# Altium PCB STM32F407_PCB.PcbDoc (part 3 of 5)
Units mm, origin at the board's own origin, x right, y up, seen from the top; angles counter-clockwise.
Board outline 100.27 x 100.27 mm, 2 copper layers (Top Layer, Bottom Layer); 134 components, 132 nets, 659 pads, 288 vias.
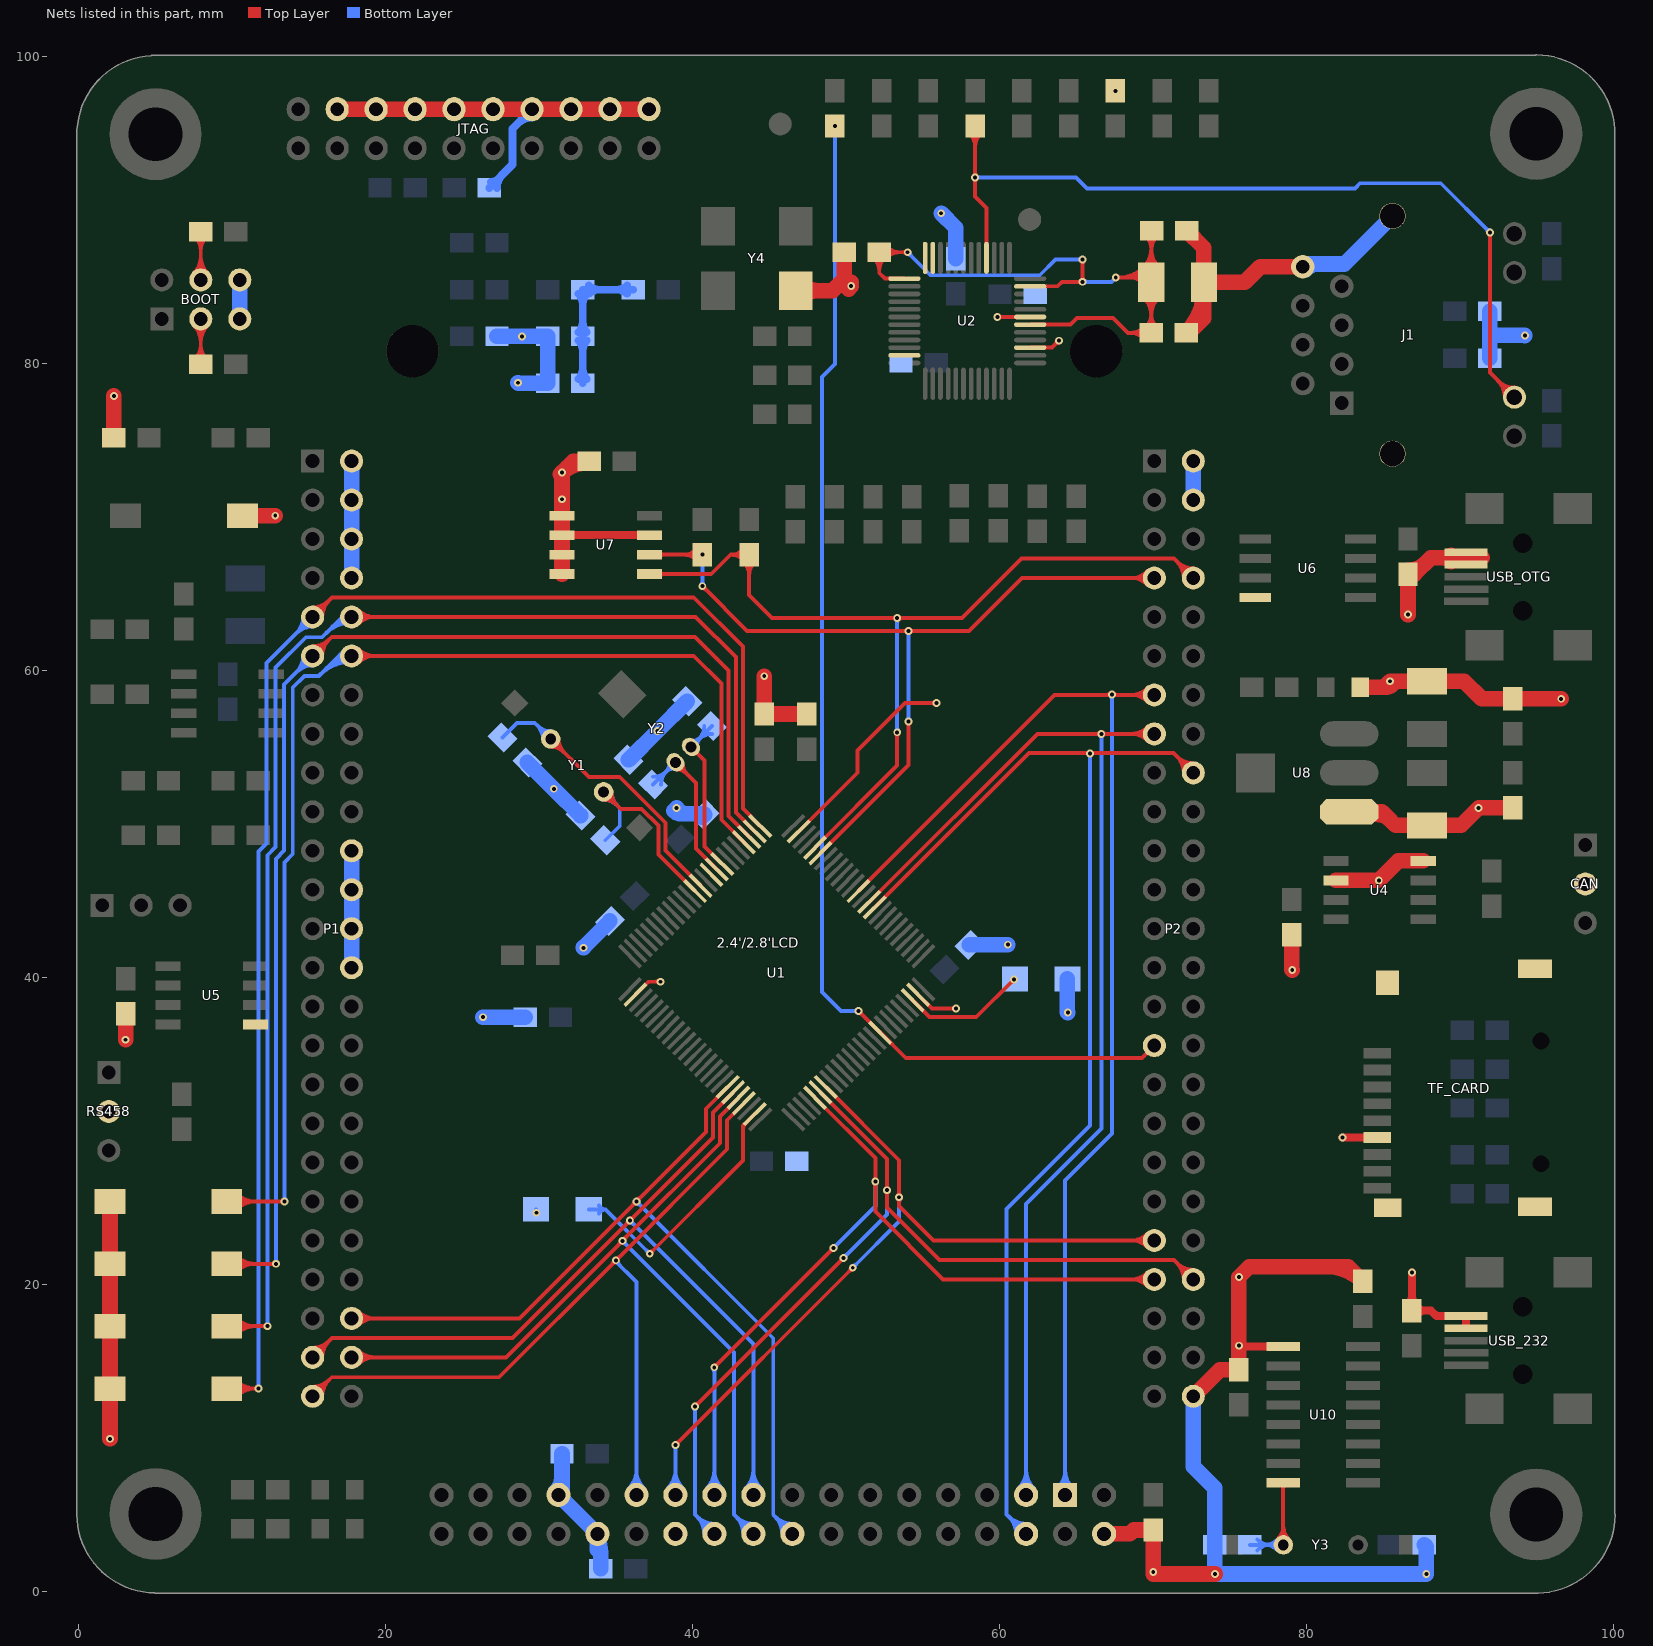
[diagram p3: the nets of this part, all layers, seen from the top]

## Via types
v1: diameter 0.508, hole 0.254, Top Layer to Bottom Layer, 288 vias

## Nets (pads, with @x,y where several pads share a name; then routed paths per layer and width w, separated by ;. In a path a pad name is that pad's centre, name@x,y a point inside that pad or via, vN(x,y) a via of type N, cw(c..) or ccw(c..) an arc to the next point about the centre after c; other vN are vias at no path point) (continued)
FSMC_D10: 2.4'/2.8'LCD.16 P1.46 U1.44 | length 76
  Top Layer w0.254: P1.46@17.78,17.78 28.715,17.78 v1(36.341,25.406) 40.869,29.933 40.869,31.444 U1.44@42.292,32.867 ; 18.671,17.78 cw(c18.671,18.671) 18.041,18.041 ccw(c18.671,18.671) 18.671,17.78 ; 18.671,17.78 ccw(c18.671,16.889) 18.041,17.519 cw(c18.671,16.889) 18.671,17.78 ; 19.284,17.78 cw(c19.284,19.284) 18.221,18.221 ccw(c19.284,19.284) 19.284,17.78 ; 19.284,17.78 ccw(c19.284,16.276) 18.221,17.339 cw(c19.284,16.276) 19.284,17.78 ; 36.125,25.189 cw(c36.341,24.972) 36.341,25.279 ccw(c36.341,24.972) 36.125,25.189 ; 36.125,25.189 ccw(c35.908,25.406) 36.214,25.406 cw(c35.908,25.406) 36.125,25.189 ; 36.558,25.623 cw(c36.341,25.84) 36.341,25.533 ccw(c36.341,25.84) 36.558,25.623 ; 36.558,25.623 ccw(c36.775,25.406) 36.468,25.406 cw(c36.775,25.406) 36.558,25.623
  Bottom Layer w0.254: v1(36.341,25.406) 45.263,16.485 45.263,4.978 2.4'/2.8'LCD.16@46.507,3.734 ; 36.558,25.189 cw(c36.775,25.406) 36.468,25.406 ccw(c36.775,25.406) 36.558,25.189 ; 36.558,25.189 ccw(c36.341,24.972) 36.341,25.279 cw(c36.341,24.972) 36.558,25.189 ; 45.38,4.861 cw(c44.253,3.734) 45.847,3.734 ccw(c44.253,3.734) 45.38,4.861 ; 45.38,4.861 ccw(c46.507,5.989) 46.507,4.394 cw(c46.507,5.989) 45.38,4.861 ; 45.814,4.428 cw(c45.12,3.734) 46.101,3.734 ccw(c45.12,3.734) 45.814,4.428 ; 45.814,4.428 ccw(c46.507,5.121) 46.507,4.14 cw(c46.507,5.121) 45.814,4.428
FSMC_D11: 2.4'/2.8'LCD.17 P1.47 U1.45 | length 75.2
  Top Layer w0.254: P1.47@15.24,15.24 16.51,16.51 28.272,16.51 v1(35.916,24.154) 41.326,29.564 41.326,31.194 U1.45@42.645,32.514 ; 15.87,15.87 cw(c15.24,16.5) 15.24,15.609 ccw(c15.24,16.5) 15.87,15.87 ; 15.87,15.87 ccw(c16.5,15.24) 15.609,15.24 cw(c16.5,15.24) 15.87,15.87 ; 16.304,16.304 cw(c15.24,17.367) 15.24,15.863 ccw(c15.24,17.367) 16.304,16.304 ; 16.304,16.304 ccw(c17.367,15.24) 15.863,15.24 cw(c17.367,15.24) 16.304,16.304 ; 35.699,23.937 cw(c35.916,23.72) 35.916,24.027 ccw(c35.916,23.72) 35.699,23.937 ; 35.699,23.937 ccw(c35.482,24.154) 35.789,24.154 cw(c35.482,24.154) 35.699,23.937 ; 36.132,24.371 cw(c35.916,24.588) 35.916,24.281 ccw(c35.916,24.588) 36.132,24.371 ; 36.132,24.371 ccw(c36.349,24.154) 36.043,24.154 cw(c36.349,24.154) 36.132,24.371
  Bottom Layer w0.254: v1@35.916,24.155 43.967,16.104 2.4'/2.8'LCD.17@43.967,6.274 ; 43.967,7.255 cw(c42.986,7.255) 43.68,6.561 ccw(c42.986,7.255) 43.967,7.255 ; 43.967,7.255 ccw(c44.949,7.255) 44.255,6.561 cw(c44.949,7.255) 43.967,7.255 ; 43.967,7.868 cw(c42.373,7.868) 43.5,6.741 ccw(c42.373,7.868) 43.967,7.868 ; 43.967,7.868 ccw(c45.562,7.868) 44.434,6.741 cw(c45.562,7.868) 43.967,7.868 ; v1@35.916,24.027 cw(c35.916,23.717) 36.135,23.936 ccw(c35.916,23.717) v1@35.916,24.027 ; v1@36.043,24.154 ccw(c36.346,24.154) 36.131,23.94 cw(c36.346,24.154) v1@36.043,24.154
FSMC_D12: 2.4'/2.8'LCD.18 P1.48 U1.46 | length 74.4
  Top Layer w0.254: P1.48@17.78,15.24 27.838,15.24 v1(35.433,22.835) ; v1@35.415,22.827 41.783,29.195 41.783,30.945 U1.46@42.999,32.16 ; 18.671,15.24 cw(c18.671,16.131) 18.041,15.501 ccw(c18.671,16.131) 18.671,15.24 ; 18.671,15.24 ccw(c18.671,14.349) 18.041,14.979 cw(c18.671,14.349) 18.671,15.24 ; 19.284,15.24 cw(c19.284,16.744) 18.221,15.681 ccw(c19.284,16.744) 19.284,15.24 ; 19.284,15.24 ccw(c19.284,13.736) 18.221,14.799 cw(c19.284,13.736) 19.284,15.24 ; 35.216,22.618 cw(c35.433,22.401) 35.433,22.708 ccw(c35.433,22.401) 35.216,22.618 ; 35.216,22.618 ccw(c34.999,22.835) 35.306,22.835 cw(c34.999,22.835) 35.216,22.618 ; v1@35.433,22.962 ccw(c35.433,23.242) 35.632,23.044 cw(c35.433,23.242) v1@35.433,22.962 ; v1@35.56,22.835 cw(c35.892,22.835) 35.657,23.07 ccw(c35.892,22.835) v1@35.56,22.835
  Bottom Layer w0.254: v1(35.433,22.835) 42.697,15.57 42.697,5.004 2.4'/2.8'LCD.18@43.967,3.734 ; 35.65,22.618 cw(c35.867,22.835) 35.56,22.835 ccw(c35.867,22.835) 35.65,22.618 ; 35.65,22.618 ccw(c35.433,22.401) 35.433,22.708 cw(c35.433,22.401) 35.65,22.618 ; 42.84,4.861 cw(c41.713,3.734) 43.307,3.734 ccw(c41.713,3.734) 42.84,4.861 ; 42.84,4.861 ccw(c43.967,5.989) 43.967,4.394 cw(c43.967,5.989) 42.84,4.861 ; 43.274,4.428 cw(c42.58,3.734) 43.561,3.734 ccw(c42.58,3.734) 43.274,4.428 ; 43.274,4.428 ccw(c43.967,5.121) 43.967,4.14 cw(c43.967,5.121) 43.274,4.428
FSMC_D13: 2.4'/2.8'LCD.19 P2.43 U1.55 | length 76.2
  Top Layer w0.254: v1(41.415,14.592) v1(49.187,22.365) ; U1.55@47.984,32.16 51.918,28.227 v1(51.918,26.695) 51.918,24.74 56.337,20.32 P2.43@70.104,20.32 ; 41.632,14.809 cw(c41.415,15.026) 41.415,14.719 ccw(c41.415,15.026) 41.632,14.809 ; 41.632,14.809 ccw(c41.848,14.592) 41.542,14.592 cw(c41.848,14.592) 41.632,14.809 ; 48.97,22.148 cw(c49.187,21.931) 49.187,22.238 ccw(c49.187,21.931) 48.97,22.148 ; 48.97,22.148 ccw(c48.753,22.365) 49.06,22.365 cw(c48.753,22.365) 48.97,22.148 ; 51.918,26.389 cw(c52.224,26.389) 52.007,26.606 ccw(c52.224,26.389) 51.918,26.389 ; 51.918,26.389 ccw(c51.611,26.389) 51.828,26.606 cw(c51.611,26.389) 51.918,26.389 ; 51.918,27.002 cw(c51.611,27.002) 51.828,26.785 ccw(c51.611,27.002) 51.918,27.002 ; 51.918,27.002 ccw(c52.224,27.002) 52.007,26.785 cw(c52.224,27.002) 51.918,27.002 ; 68.6,20.32 cw(c68.6,18.816) 69.663,19.879 ccw(c68.6,18.816) 68.6,20.32 ; 68.6,20.32 ccw(c68.6,21.824) 69.663,20.761 cw(c68.6,21.824) 68.6,20.32 ; 69.213,20.32 cw(c69.213,19.429) 69.843,20.059 ccw(c69.213,19.429) 69.213,20.32 ; 69.213,20.32 ccw(c69.213,21.211) 69.843,20.581 cw(c69.213,21.211) 69.213,20.32
  Bottom Layer w0.254: 2.4'/2.8'LCD.19@41.427,6.274 v1@41.427,14.592 ; v1(49.187,22.365) 51.918,25.095 v1(51.918,26.695) ; 41.427,7.255 cw(c40.446,7.255) 41.14,6.561 ccw(c40.446,7.255) 41.427,7.255 ; 41.427,7.255 ccw(c42.409,7.255) 41.715,6.561 cw(c42.409,7.255) 41.427,7.255 ; 41.427,7.868 cw(c39.833,7.868) 40.96,6.741 ccw(c39.833,7.868) 41.427,7.868 ; 41.427,7.868 ccw(c43.022,7.868) 41.894,6.741 cw(c43.022,7.868) 41.427,7.868 ; 49.404,22.582 cw(c49.187,22.798) 49.187,22.492 ccw(c49.187,22.798) 49.404,22.582 ; 49.404,22.582 ccw(c49.621,22.365) 49.314,22.365 cw(c49.621,22.365) 49.404,22.582 ; 51.918,26.389 cw(c52.224,26.389) 52.007,26.606 ccw(c52.224,26.389) 51.918,26.389 ; 51.918,26.389 ccw(c51.611,26.389) 51.828,26.606 cw(c51.611,26.389) 51.918,26.389 ; v1@41.325,14.502 cw(c41.077,14.255) 41.427,14.255 ccw(c41.077,14.255) v1@41.325,14.502 ; 41.427,14.316 cw(c41.691,14.316) 41.505,14.502 ccw(c41.691,14.316) 41.427,14.316
FSMC_D14: 2.4'/2.8'LCD.20 P2.44 U1.56 | length 81.7
  Top Layer w0.254: v1(40.157,12.04) v1(49.835,21.717) ; U1.56@48.338,32.514 52.68,28.172 v1(52.68,26.137) 52.68,25.019 56.109,21.59 71.374,21.59 P2.44@72.644,20.32 ; 40.374,12.256 cw(c40.157,12.473) 40.157,12.167 ccw(c40.157,12.473) 40.374,12.256 ; 40.374,12.256 ccw(c40.591,12.04) 40.284,12.04 cw(c40.591,12.04) 40.374,12.256 ; 49.618,21.5 cw(c49.835,21.283) 49.835,21.59 ccw(c49.835,21.283) 49.618,21.5 ; 49.618,21.5 ccw(c49.401,21.717) 49.708,21.717 cw(c49.401,21.717) 49.618,21.5 ; 52.68,25.83 cw(c52.986,25.83) 52.769,26.047 ccw(c52.986,25.83) 52.68,25.83 ; 52.68,25.83 ccw(c52.373,25.83) 52.59,26.047 cw(c52.373,25.83) 52.68,25.83 ; 52.68,26.443 cw(c52.373,26.443) 52.59,26.226 ccw(c52.373,26.443) 52.68,26.443 ; 52.68,26.443 ccw(c52.986,26.443) 52.769,26.226 cw(c52.986,26.443) 52.68,26.443 ; 71.58,21.384 cw(c70.517,20.32) 72.021,20.32 ccw(c70.517,20.32) 71.58,21.384 ; 71.58,21.384 ccw(c72.644,22.447) 72.644,20.943 cw(c72.644,22.447) 71.58,21.384 ; 72.014,20.95 cw(c71.384,20.32) 72.275,20.32 ccw(c71.384,20.32) 72.014,20.95 ; 72.014,20.95 ccw(c72.644,21.58) 72.644,20.689 cw(c72.644,21.58) 72.014,20.95
  Bottom Layer w0.254: v1(40.157,12.04) 40.157,5.004 2.4'/2.8'LCD.20@41.427,3.734 ; v1(49.835,21.717) 52.68,24.562 v1(52.68,26.137) ; 40.157,11.733 cw(c40.464,11.733) 40.247,11.95 ccw(c40.464,11.733) 40.157,11.733 ; 40.157,11.733 ccw(c39.851,11.733) 40.068,11.95 cw(c39.851,11.733) 40.157,11.733 ; 40.3,4.861 cw(c39.173,3.734) 40.767,3.734 ccw(c39.173,3.734) 40.3,4.861 ; 40.3,4.861 ccw(c41.427,5.989) 41.427,4.394 cw(c41.427,5.989) 40.3,4.861 ; 40.734,4.428 cw(c40.04,3.734) 41.021,3.734 ccw(c40.04,3.734) 40.734,4.428 ; 40.734,4.428 ccw(c41.427,5.121) 41.427,4.14 cw(c41.427,5.121) 40.734,4.428 ; 50.052,21.934 cw(c49.835,22.151) 49.835,21.844 ccw(c49.835,22.151) 50.052,21.934 ; 50.052,21.934 ccw(c50.268,21.717) 49.962,21.717 cw(c50.268,21.717) 50.052,21.934 ; 52.68,25.83 cw(c52.986,25.83) 52.769,26.047 ccw(c52.986,25.83) 52.68,25.83 ; 52.68,25.83 ccw(c52.373,25.83) 52.59,26.047 cw(c52.373,25.83) 52.68,25.83
FSMC_D15: 2.4'/2.8'LCD.21 P2.41 U1.57 | length 75.1
  Top Layer w0.254: v1(38.887,9.525) v1(50.444,21.082) ; U1.57@48.691,32.867 53.467,28.092 53.467,25.095 55.702,22.86 P2.41@70.104,22.86 ; 39.104,9.742 cw(c38.887,9.959) 38.887,9.652 ccw(c38.887,9.959) 39.104,9.742 ; 39.104,9.742 ccw(c39.321,9.525) 39.014,9.525 cw(c39.321,9.525) 39.104,9.742 ; 50.228,20.865 cw(c50.444,20.648) 50.444,20.955 ccw(c50.444,20.648) 50.228,20.865 ; 50.228,20.865 ccw(c50.011,21.082) 50.317,21.082 cw(c50.011,21.082) 50.228,20.865 ; 53.467,25.373 cw(c53.774,25.373) 53.557,25.59 ccw(c53.774,25.373) 53.467,25.373 ; 53.467,25.373 ccw(c53.16,25.373) 53.377,25.59 cw(c53.16,25.373) 53.467,25.373 ; 53.467,25.986 cw(c53.16,25.986) 53.377,25.769 ccw(c53.16,25.986) 53.467,25.986 ; 53.467,25.986 ccw(c53.774,25.986) 53.557,25.769 cw(c53.774,25.986) 53.467,25.986 ; 68.6,22.86 cw(c68.6,21.356) 69.663,22.419 ccw(c68.6,21.356) 68.6,22.86 ; 68.6,22.86 ccw(c68.6,24.364) 69.663,23.301 cw(c68.6,24.364) 68.6,22.86 ; 69.213,22.86 cw(c69.213,21.969) 69.843,22.599 ccw(c69.213,21.969) 69.213,22.86 ; 69.213,22.86 ccw(c69.213,23.751) 69.843,23.121 cw(c69.213,23.751) 69.213,22.86
  Bottom Layer w0.254: 2.4'/2.8'LCD.21@38.887,6.274 v1(38.887,9.525) ; v1(50.444,21.082) 53.467,24.105 v1(53.467,25.679) ; 38.887,7.255 cw(c37.906,7.255) 38.6,6.561 ccw(c37.906,7.255) 38.887,7.255 ; 38.887,7.255 ccw(c39.869,7.255) 39.175,6.561 cw(c39.869,7.255) 38.887,7.255 ; 38.887,7.868 cw(c37.293,7.868) 38.42,6.741 ccw(c37.293,7.868) 38.887,7.868 ; 38.887,7.868 ccw(c40.482,7.868) 39.354,6.741 cw(c40.482,7.868) 38.887,7.868 ; 38.887,9.218 cw(c39.194,9.218) 38.977,9.435 ccw(c39.194,9.218) 38.887,9.218 ; 38.887,9.218 ccw(c38.581,9.218) 38.798,9.435 cw(c38.581,9.218) 38.887,9.218 ; 50.661,21.299 cw(c50.444,21.516) 50.444,21.209 ccw(c50.444,21.516) 50.661,21.299 ; 50.661,21.299 ccw(c50.878,21.082) 50.571,21.082 cw(c50.878,21.082) 50.661,21.299 ; 53.467,25.373 cw(c53.774,25.373) 53.557,25.59 ccw(c53.774,25.373) 53.467,25.373 ; 53.467,25.373 ccw(c53.16,25.373) 53.377,25.59 cw(c53.16,25.373) 53.467,25.373
FSMC_NE1: 2.4'/2.8'LCD.1 P2.13 U1.88 | length 95.8
  Top Layer w0.254: U1.88@50.812,45.631 63.602,58.42 P2.13@70.104,58.42 ; 68.6,58.42 cw(c68.6,56.916) 69.663,57.979 ccw(c68.6,56.916) 68.6,58.42 ; 68.6,58.42 ccw(c68.6,59.924) 69.663,58.861 cw(c68.6,59.924) 68.6,58.42 ; 69.213,58.42 cw(c69.213,57.529) 69.843,58.159 ccw(c69.213,57.529) 69.213,58.42 ; 69.213,58.42 ccw(c69.213,59.311) 69.843,58.681 cw(c69.213,59.311) 69.213,58.42 ; 66.967,58.42 ccw(c66.967,58.813) 67.246,58.535 cw(c66.967,58.813) 66.967,58.42 ; v1@67.425,58.535 ccw(c67.703,58.813) 67.703,58.42 cw(c67.703,58.813) v1@67.425,58.535
  Bottom Layer w0.254: 2.4'/2.8'LCD.1@64.287,6.274 64.287,26.772 67.335,29.82 v1(67.335,58.445) ; 64.287,7.255 cw(c63.306,7.255) 64,6.561 ccw(c63.306,7.255) 64.287,7.255 ; 64.287,7.255 ccw(c65.269,7.255) 64.575,6.561 cw(c65.269,7.255) 64.287,7.255 ; 64.287,7.868 cw(c62.693,7.868) 63.82,6.741 ccw(c62.693,7.868) 64.287,7.868 ; 64.287,7.868 ccw(c65.882,7.868) 64.754,6.741 cw(c65.882,7.868) 64.287,7.868 ; 67.335,58.139 cw(c67.642,58.139) 67.425,58.356 ccw(c67.642,58.139) 67.335,58.139 ; 67.335,58.139 ccw(c67.029,58.139) 67.246,58.356 cw(c67.029,58.139) 67.335,58.139
FSMC_NOE: 2.4'/2.8'LCD.4 P2.18 U1.85 | length 96.9
  Top Layer w0.254: U1.85@51.873,44.57 61.938,54.635 71.349,54.635 P2.18@72.644,53.34 ; 71.58,54.404 cw(c70.517,53.34) 72.021,53.34 ccw(c70.517,53.34) 71.58,54.404 ; 71.58,54.404 ccw(c72.644,55.467) 72.644,53.963 cw(c72.644,55.467) 71.58,54.404 ; 72.014,53.97 cw(c71.384,53.34) 72.275,53.34 ccw(c71.384,53.34) 72.014,53.97 ; 72.014,53.97 ccw(c72.644,54.6) 72.644,53.709 cw(c72.644,54.6) 72.014,53.97 ; 65.545,54.635 cw(c65.545,54.242) 65.823,54.52 ccw(c65.545,54.242) 65.545,54.635 ; v1@66.003,54.52 cw(c66.281,54.242) 66.281,54.635 ccw(c66.281,54.242) v1@66.003,54.52
  Bottom Layer w0.254: 2.4'/2.8'LCD.4@61.747,3.734 60.477,5.004 60.477,24.917 65.913,30.353 v1(65.913,54.61) ; 60.62,4.861 cw(c59.493,3.734) 61.087,3.734 ccw(c59.493,3.734) 60.62,4.861 ; 60.62,4.861 ccw(c61.747,5.989) 61.747,4.394 cw(c61.747,5.989) 60.62,4.861 ; 61.054,4.428 cw(c60.36,3.734) 61.341,3.734 ccw(c60.36,3.734) 61.054,4.428 ; 61.054,4.428 ccw(c61.747,5.121) 61.747,4.14 cw(c61.747,5.121) 61.054,4.428 ; 65.913,54.303 cw(c66.22,54.303) 66.003,54.52 ccw(c66.22,54.303) 65.913,54.303 ; 65.913,54.303 ccw(c65.606,54.303) 65.823,54.52 cw(c65.606,54.303) 65.913,54.303
FSMC_NWE: 2.4'/2.8'LCD.3 P2.15 U1.86 | length 93.3
  Top Layer w0.254: U1.86@51.519,44.924 62.476,55.88 v1(66.65,55.88) P2.15@70.104,55.88 ; 66.343,55.88 cw(c66.343,55.573) 66.56,55.79 ccw(c66.343,55.573) 66.343,55.88 ; 66.343,55.88 ccw(c66.343,56.187) 66.56,55.97 cw(c66.343,56.187) 66.343,55.88 ; 66.956,55.88 cw(c66.956,56.187) 66.739,55.97 ccw(c66.956,56.187) 66.956,55.88 ; 66.956,55.88 ccw(c66.956,55.573) 66.739,55.79 cw(c66.956,55.573) 66.956,55.88 ; 68.6,55.88 cw(c68.6,54.376) 69.663,55.439 ccw(c68.6,54.376) 68.6,55.88 ; 68.6,55.88 ccw(c68.6,57.384) 69.663,56.321 cw(c68.6,57.384) 68.6,55.88 ; 69.213,55.88 cw(c69.213,54.989) 69.843,55.619 ccw(c69.213,54.989) 69.213,55.88 ; 69.213,55.88 ccw(c69.213,56.771) 69.843,56.141 cw(c69.213,56.771) 69.213,55.88
  Bottom Layer w0.254: 2.4'/2.8'LCD.3@61.747,6.274 61.747,25.248 66.65,30.15 v1(66.65,55.88) ; 61.747,7.255 cw(c60.766,7.255) 61.46,6.561 ccw(c60.766,7.255) 61.747,7.255 ; 61.747,7.255 ccw(c62.729,7.255) 62.035,6.561 cw(c62.729,7.255) 61.747,7.255 ; 61.747,7.868 cw(c60.153,7.868) 61.28,6.741 ccw(c60.153,7.868) 61.747,7.868 ; 61.747,7.868 ccw(c63.342,7.868) 62.214,6.741 cw(c63.342,7.868) 61.747,7.868 ; 66.65,55.573 cw(c66.956,55.573) 66.739,55.79 ccw(c66.956,55.573) 66.65,55.573 ; 66.65,55.573 ccw(c66.343,55.573) 66.56,55.79 cw(c66.343,55.573) 66.65,55.573
GND: 2.4'/2.8'LCD.22 2.4'/2.8'LCD.26 2.4'/2.8'LCD.27 2.4'/2.8'LCD.36 BOOT.5 BOOT.6 C1.1 C2.2 C3.2 C4.2 C5.2 C6.2 C7.2 C8.2 C9.2 C10.2 C11.2 C12.2 C13.1 C14.1 C15.2 C16.1 C17.1 C18.1 C20.2 C21.2 C22.2 C23.2 C24.2 C25.2 C26.2 C27.2 C28.2 C29.1 C30.1 C31.1 C32.2 C33.2 C36.1 C37.2 C38.2 C39.2 C40.2 C41.2 C42.1 C43.1 C44.2 CAN.2 DS0.2 J1.8 J1.13 J1.14 JTAG.4 JTAG.6 JTAG.8 JTAG.10 JTAG.12 JTAG.14 JTAG.16 JTAG.18 JTAG.20 K1.2 K2.2 K3.2 K4.2 P1.2 P1.4 P1.6 P1.8 P1.22 P1.24 P1.26 P1.28 P2.2 P2.4 P2.50 R3.2 R16.1 R32.1 RESET.2 RS458.2 TF_CARD.6 TF_CARD.10 TF_CARD.11 TF_CARD.12 TF_CARD.13 U1.10 U1.27 U1.74 U1.99 U2.15 U2.19 U2.35 U2.36 U2.47 U4.2 U4.8 U5.5 U6.4 U7.1 U7.2 U7.3 U7.4 U7.7 U8.1 U10.1 USB_232.4 USB_232.5 USB_OTG.4 USB_OTG.5 Y4.2 | length 374.5
  Top Layer w0.254: U1.27@36.281,38.878 37.129,39.726 v1(37.922,39.726) ; U1.99@46.923,49.52 50.749,53.346 50.749,54.788 53.848,57.887 v1(55.905,57.887) ; U1.74@54.701,38.878 55.606,37.973 v1(57.175,37.973) ; v1(59.868,83.058) 59.872,83.054 U2.19@62.012,83.054 ; U2.15@62.012,81.054 63.426,81.054 v1(63.881,81.509) ; 37.616,39.726 cw(c37.616,39.419) 37.832,39.636 ccw(c37.616,39.419) 37.616,39.726 ; 37.616,39.726 ccw(c37.616,40.032) 37.832,39.815 cw(c37.616,40.032) 37.616,39.726 ; 55.599,57.887 cw(c55.599,57.58) 55.816,57.797 ccw(c55.599,57.58) 55.599,57.887 ; 55.599,57.887 ccw(c55.599,58.193) 55.816,57.976 cw(c55.599,58.193) 55.599,57.887 ; 56.869,37.973 cw(c56.869,37.666) 57.086,37.883 ccw(c56.869,37.666) 56.869,37.973 ; 56.869,37.973 ccw(c56.869,38.28) 57.086,38.063 cw(c56.869,38.28) 56.869,37.973 ; 63.664,81.292 cw(c63.881,81.075) 63.881,81.382 ccw(c63.881,81.075) 63.664,81.292 ; 63.664,81.292 ccw(c63.447,81.509) 63.754,81.509 cw(c63.447,81.509) 63.664,81.292 ; v1@59.958,82.968 cw(c60.165,82.761) 60.165,83.054 ccw(c60.165,82.761) v1@59.958,82.968 ; v1@59.958,83.148 ccw(c60.184,83.374) 60.184,83.054 cw(c60.184,83.374) v1@59.958,83.148
  Top Layer w0.508: U7.2@31.496,68.834 U7.7@37.196,68.834 ; v1@75.617,15.951 U10.1@78.502,15.951 ; v1(82.372,29.566) 82.374,29.564 TF_CARD.6@84.633,29.564 ; v1(86.893,20.777) 86.892,20.776 C42.1@86.892,18.288 88.138,18.288 88.494,17.932 USB_232.5@90.424,17.932 USB_232.4@90.424,17.132 ; 86.892,19.335 cw(c85.972,19.335) 86.622,18.684 ccw(c85.972,19.335) 86.892,19.335 ; 86.892,19.335 ccw(c87.812,19.335) 87.161,18.684 cw(c87.812,19.335) 86.892,19.335 ; 87.812,18.288 cw(c87.812,19.208) 87.161,18.557 ccw(c87.812,19.208) 87.812,18.288 ; 87.812,18.288 ccw(c87.812,17.368) 87.161,18.019 cw(c87.812,17.368) 87.812,18.288
  Top Layer w1.016: v1(2.032,9.931) K4.2@2.032,25.4 ; C7.2@2.286,75.186 v1(2.286,77.902) ; C37.2@3.046,37.643 3.046,35.943 v1(3.048,35.941) ; RESET.2@10.668,70.104 v1(12.802,70.104) ; JTAG.4@16.84,96.596 JTAG.10@24.46,96.596 JTAG.12@27,96.596 JTAG.16@32.08,96.596 JTAG.18@34.62,96.596 JTAG.20@37.16,96.596 ; U7.4@31.496,66.294 U7.3@31.496,67.564 U7.2@31.496,68.834 U7.1@31.496,70.104 v1(31.496,71.171) v1(31.496,72.923) 32.234,73.662 C39.2@33.274,73.662 ; v1(44.677,59.641) C13.1@44.677,57.175 C14.1@47.446,57.175 ; Y4.2@46.736,84.768 49.132,84.768 49.886,85.522 ; C20.2@49.886,87.276 49.886,85.522 ; v1(50.343,85.065) 49.886,85.522 ; 2.4'/2.8'LCD.36@66.827,3.734 68.504,3.734 68.758,3.988 C30.1@70.029,3.988 v1(70.029,1.246) 70.029,1.118 v1(74.066,1.118) ; C21.2@72.187,82.015 72.363,82.015 73.33,82.982 C23.2@73.33,85.319 ; C22.2@72.212,88.67 73.33,87.552 C23.2@73.33,85.319 ; P2.50@72.644,12.7 74.371,14.427 C44.2@75.617,14.427 75.617,15.292 v1(75.617,16.002) v1(75.617,20.474) 76.302,21.158 82.726,21.158 C43.1@83.691,20.193 ; C36.1@79.072,42.799 79.072,40.511 v1(79.096,40.488) ; J1.8@79.781,86.33 77.008,86.33 75.997,85.319 C23.2@73.33,85.319 ; U4.2@81.94,46.33 v1(84.734,46.33) 86.004,47.6 U4.8@87.64,47.6 ; U8.1@82.806,50.801 84.937,50.801 85.827,49.911 C10.2@87.884,49.911 90.094,49.911 v1(91.237,51.054) C11.2@93.47,51.054 ; DS0.2@83.515,58.928 85.09,58.928 ; v1(86.639,63.652) 86.638,63.654 C38.2@86.638,66.294 87.071,66.294 88.138,67.361 91.465,67.361 ; v1(96.622,58.166) 91.44,58.166 90.297,59.309 C8.2@87.884,59.309 v1(85.471,59.309) ; 48.165,84.768 cw(c48.165,86.197) 47.155,85.187 ccw(c48.165,86.197) 48.165,84.768 ; 48.165,84.768 ccw(c48.165,83.339) 47.155,84.349 cw(c48.165,83.339) 48.165,84.768 ; 49.886,85.522 ccw(c50.756,85.522) 50.173,84.876 cw(c50.756,85.522) 49.886,85.522 ; 85.09,58.928 v1(85.471,59.309) ; 85.09,58.928 v1(85.471,59.309) ; 85.164,58.928 ccw(c85.164,59.616) v1@85.651,59.129 ; 85.164,58.928 ccw(c85.164,59.616) v1@85.651,59.129 ; 85.164,58.928 ccw(c85.164,59.616) v1@85.651,59.129 ; 85.164,58.928 ccw(c85.164,59.616) v1@85.651,59.129 ; v1@31.372,72.799 cw(c33.147,71.024) 33.147,73.535 ccw(c33.147,71.024) v1@31.372,72.799 ; 31.778,73.205 cw(c32.724,72.259) 33.11,73.54 ccw(c32.724,72.259) 31.778,73.205 ; 49.215,84.852 cw(c50.343,83.724) 50.343,85.319 ccw(c50.343,83.724) 49.215,84.852 ; 49.886,85.555 ccw(c50.833,85.555) 50.163,84.885 cw(c50.833,85.555) 49.886,85.555 ; C21.2@72.224,82.105 ccw(c69.554,84.774) 73.33,84.774 cw(c69.554,84.774) C21.2@72.224,82.105 ; 81.361,21.158 cw(c81.361,17.99) 83.602,20.23 ccw(c81.361,17.99) 81.361,21.158 ; U8.1@84.024,50.515 cw(c84.575,49.387) 85.463,50.275 ccw(c84.575,49.387) U8.1@84.024,50.515 ; C38.2@86.638,66.548 ccw(c86.638,68.208) 87.811,67.034 cw(c86.638,68.208) C38.2@86.638,66.548 ; 88.823,67.361 cw(c88.823,66.465) 89.456,67.098 ccw(c88.823,66.465) 88.823,67.361 ; 89.039,67.361 ccw(c89.039,67.95) 89.456,67.534 cw(c89.039,67.95) 89.039,67.361
  Bottom Layer w0.254: C5.2@29.809,24.881 29.809,24.674 v1(29.82,24.663) C5.2@29.82,24.638
  Bottom Layer w0.508: P1.6@17.78,68.58 P1.4@17.78,71.12 ; R3.2@26.746,91.467 28.27,92.991 28.27,95.326 JTAG.14@29.54,96.596 ; 17.78,69.777 cw(c16.583,69.777) 17.429,68.931 ccw(c16.583,69.777) 17.78,69.777 ; 17.78,69.777 ccw(c18.977,69.777) 18.131,68.931 cw(c18.977,69.777) 17.78,69.777 ; 17.78,69.923 cw(c18.977,69.923) 18.131,70.769 ccw(c18.977,69.923) 17.78,69.923 ; 17.78,69.923 ccw(c16.583,69.923) 17.429,70.769 cw(c16.583,69.923) 17.78,69.923 ; R3.2@26.873,91.848 ccw(c26.873,92.461) 27.307,92.028 cw(c26.873,92.461) R3.2@26.873,91.848 ; R3.2@27.254,91.467 cw(c28.481,91.467) 27.613,92.334 ccw(c28.481,91.467) R3.2@27.254,91.467 ; 28.63,95.686 cw(c29.54,94.775) 29.54,96.063 ccw(c29.54,94.775) 28.63,95.686 ; 28.72,95.776 ccw(c27.937,96.559) 29.044,96.559 cw(c27.937,96.559) 28.72,95.776
  Bottom Layer w1.016: BOOT.5@10.49,82.931 BOOT.6@10.49,85.471 ; P1.28@17.78,40.64 P1.26@17.78,43.18 P1.24@17.78,45.72 P1.22@17.78,48.26 ; P1.8@17.78,66.04 P1.6@17.78,68.58 P1.4@17.78,71.12 P1.2@17.78,73.66 ; v1(26.34,37.414) 26.341,37.413 C12.2@29.108,37.413 ; R32.1@27.254,81.786 v1(28.88,81.786) C32.2@30.556,81.786 C33.2@30.556,78.738 28.653,78.738 v1(28.626,78.765) ; C1.1@29.234,54.025 v1(30.961,52.297) C2.2@32.698,50.561 ; 2.4'/2.8'LCD.27@31.267,6.274 2.4'/2.8'LCD.26@33.807,3.734 33.807,2.692 34.011,2.489 C29.1@34.011,1.449 ; 2.4'/2.8'LCD.27@31.496,6.502 C31.1@31.496,8.968 ; v1(32.893,41.935) 32.893,41.963 C16.1@34.619,43.689 ; C4.2@35.822,54.193 35.847,54.193 v1(37.728,56.074) C3.2@39.657,58.003 ; v1(38.964,51.054) 39.339,50.678 40.736,50.678 C17.1@40.794,50.621 ; v1(56.21,89.814) 57.148,88.876 C25.2@57.148,86.843 ; C15.2@58.054,42.131 60.546,42.131 v1(60.554,42.139) ; C6.2@64.44,39.903 64.44,37.744 v1(64.465,37.719) ; P2.50@72.644,12.7 72.644,8.128 74.041,6.731 C40.2@74.041,3.021 74.041,1.143 v1(74.066,1.118) v1(87.833,1.118) 87.833,2.897 C41.2@87.706,3.024 ; P2.4@72.644,71.12 P2.2@72.644,73.66 ; J1.8@79.781,86.33 79.959,86.507 82.491,86.507 J1.14@85.623,89.64 ; C28.2@91.973,80.367 91.973,81.864 ; C27.2@91.973,83.415 91.973,81.864 ; v1(94.259,81.839) 94.234,81.864 91.973,81.864 ; 2.4'/2.8'LCD.26@33.61,3.536 cw(c32.642,2.569) 34.011,2.569 ; 2.4'/2.8'LCD.26@33.61,3.536 cw(c32.642,2.569) 34.011,2.569 ; 2.4'/2.8'LCD.26@33.61,3.536 cw(c32.642,2.569) 34.011,2.569 ; 2.4'/2.8'LCD.26@33.61,3.536 cw(c32.642,2.569) 34.011,2.569 ; 38.784,50.874 ccw(c39.258,51.348) 39.258,50.678 ; 38.784,50.874 ccw(c39.258,51.348) 39.258,50.678 ; 38.784,50.874 ccw(c39.258,51.348) 39.258,50.678 ; 38.784,50.874 ccw(c39.258,51.348) 39.258,50.678 ; 2.4'/2.8'LCD.27@31.07,6.471 ccw(c30.041,7.5) 31.496,7.5 cw(c30.041,7.5) 2.4'/2.8'LCD.27@31.07,6.471 ; C17.1@40.042,50.678 cw(c40.042,49.87) 40.614,50.441 ccw(c40.042,49.87) C17.1@40.042,50.678 ; J1.8@79.961,86.15 cw(c80.824,85.287) 80.824,86.507 ccw(c80.824,85.287) J1.8@79.961,86.15
  other v1: 67.564,97.79
IIC_SCL: P2.7 R38.1 U1.95 U7.6 | length 76
  Top Layer w0.254: U7.6@37.196,67.564 v1(40.642,67.564) ; v1(40.64,65.507) 43.561,62.586 58.014,62.586 61.468,66.04 P2.7@70.104,66.04 ; U1.95@48.338,48.106 54.077,53.845 v1(54.077,56.693) ; 38.164,67.564 cw(c38.164,68.024) 37.839,67.699 ccw(c38.164,68.024) 38.164,67.564 ; 38.164,67.564 ccw(c38.164,67.104) 37.839,67.429 cw(c38.164,67.104) 38.164,67.564 ; 39.415,67.564 cw(c39.415,66.338) 40.282,67.205 ccw(c39.415,66.338) 39.415,67.564 ; 39.415,67.564 ccw(c39.415,68.79) 40.282,67.923 cw(c39.415,68.79) 39.415,67.564 ; R38.1@40.335,67.564 cw(c40.335,67.257) 40.552,67.474 ccw(c40.335,67.257) R38.1@40.335,67.564 ; R38.1@40.335,67.564 ccw(c40.335,67.871) 40.552,67.654 cw(c40.335,67.871) R38.1@40.335,67.564 ; 40.857,65.29 cw(c41.074,65.507) 40.767,65.507 ccw(c41.074,65.507) 40.857,65.29 ; 40.857,65.29 ccw(c40.64,65.073) 40.64,65.38 cw(c40.64,65.073) 40.857,65.29 ; 53.77,62.586 cw(c53.77,62.279) 53.987,62.496 ccw(c53.77,62.279) 53.77,62.586 ; 53.77,62.586 ccw(c53.77,62.892) 53.987,62.675 cw(c53.77,62.892) 53.77,62.586 ; 54.077,56.386 cw(c54.383,56.386) 54.166,56.603 ccw(c54.383,56.386) 54.077,56.386 ; 54.077,56.386 ccw(c53.77,56.386) 53.987,56.603 cw(c53.77,56.386) 54.077,56.386 ; 54.383,62.586 cw(c54.383,62.892) 54.166,62.675 ccw(c54.383,62.892) 54.383,62.586 ; 54.383,62.586 ccw(c54.383,62.279) 54.166,62.496 cw(c54.383,62.279) 54.383,62.586 ; 68.6,66.04 cw(c68.6,64.536) 69.663,65.599 ccw(c68.6,64.536) 68.6,66.04 ; 68.6,66.04 ccw(c68.6,67.544) 69.663,66.481 cw(c68.6,67.544) 68.6,66.04 ; 69.213,66.04 cw(c69.213,65.149) 69.843,65.779 ccw(c69.213,65.149) 69.213,66.04 ; 69.213,66.04 ccw(c69.213,66.931) 69.843,66.301 cw(c69.213,66.931) 69.213,66.04
  Bottom Layer w0.254: v1(40.64,65.507) 40.642,65.508 v1(40.642,67.564) ; v1(54.077,56.693) v1(54.077,62.586) ; 40.642,67.257 cw(c40.948,67.257) 40.731,67.474 ccw(c40.948,67.257) 40.642,67.257 ; 40.642,67.257 ccw(c40.335,67.257) 40.552,67.474 cw(c40.335,67.257) 40.642,67.257 ; 54.077,56.999 cw(c53.77,56.999) 53.987,56.783 ccw(c53.77,56.999) 54.077,56.999 ; 54.077,56.999 ccw(c54.383,56.999) 54.166,56.783 cw(c54.383,56.999) 54.077,56.999 ; 54.077,62.279 cw(c54.383,62.279) 54.166,62.496 ccw(c54.383,62.279) 54.077,62.279 ; 54.077,62.279 ccw(c53.77,62.279) 53.987,62.496 cw(c53.77,62.279) 54.077,62.279 ; v1@40.55,65.596 ccw(c40.329,65.817) 40.642,65.817 cw(c40.329,65.817) v1@40.55,65.596 ; 40.642,65.809 ccw(c40.943,65.809) 40.73,65.596 cw(c40.943,65.809) 40.642,65.809
IIC_SDA: P2.8 R37.1 U1.96 U7.5 | length 79.9
  Top Layer w0.254: U7.5@37.196,66.294 41.224,66.294 42.494,67.564 ; U1.96@47.984,48.459 53.34,53.815 v1(53.34,55.982) ; P2.8@72.644,66.04 71.374,67.31 61.443,67.31 57.556,63.424 v1(53.34,63.424) 45.187,63.424 43.69,64.921 R37.1@43.69,67.564 42.494,67.564 ; 38.164,66.294 cw(c38.164,66.754) 37.839,66.429 ccw(c38.164,66.754) 38.164,66.294 ; 38.164,66.294 ccw(c38.164,65.834) 37.839,66.159 cw(c38.164,65.834) 38.164,66.294 ; 42.494,67.564 cw(c42.494,66.412) 43.324,67.211 ccw(c42.494,66.412) 42.494,67.564 ; 42.494,67.564 ccw(c42.494,68.716) 43.324,67.917 cw(c42.494,68.716) 42.494,67.564 ; 43.69,66.211 cw(c44.916,66.211) 44.049,67.078 ccw(c44.916,66.211) 43.69,66.211 ; 43.69,66.211 ccw(c42.463,66.211) 43.33,67.078 cw(c42.463,66.211) 43.69,66.211 ; 53.033,63.424 cw(c53.033,63.117) 53.25,63.334 ccw(c53.033,63.117) 53.033,63.424 ; 53.033,63.424 ccw(c53.033,63.73) 53.25,63.514 cw(c53.033,63.73) 53.033,63.424 ; 53.34,55.675 cw(c53.647,55.675) 53.43,55.892 ccw(c53.647,55.675) 53.34,55.675 ; 53.34,55.675 ccw(c53.033,55.675) 53.25,55.892 cw(c53.033,55.675) 53.34,55.675 ; 53.647,63.424 cw(c53.647,63.73) 53.43,63.514 ccw(c53.647,63.73) 53.647,63.424 ; 53.647,63.424 ccw(c53.647,63.117) 53.43,63.334 cw(c53.647,63.117) 53.647,63.424 ; 71.58,67.104 cw(c70.517,66.04) 72.021,66.04 ccw(c70.517,66.04) 71.58,67.104 ; 71.58,67.104 ccw(c72.644,68.167) 72.644,66.663 cw(c72.644,68.167) 71.58,67.104 ; 72.014,66.67 cw(c71.384,66.04) 72.275,66.04 ccw(c71.384,66.04) 72.014,66.67 ; 72.014,66.67 ccw(c72.644,67.3) 72.644,66.409 cw(c72.644,67.3) 72.014,66.67
  Bottom Layer w0.254: v1(53.34,55.982) v1(53.34,63.424) ; 53.34,56.288 cw(c53.033,56.288) 53.25,56.071 ccw(c53.033,56.288) 53.34,56.288 ; 53.34,56.288 ccw(c53.647,56.288) 53.43,56.071 cw(c53.647,56.288) 53.34,56.288 ; 53.34,63.117 cw(c53.647,63.117) 53.43,63.334 ccw(c53.647,63.117) 53.34,63.117 ; 53.34,63.117 ccw(c53.033,63.117) 53.25,63.334 cw(c53.033,63.117) 53.34,63.117
KEY1: K1.1 P1.9 U1.1 | length 121.1
  Top Layer w0.254: K1.1@9.652,13.208 v1(11.709,13.208) ; P1.9@15.24,63.5 16.51,64.77 40.081,64.77 43.282,61.57 43.282,51.005 U1.1@44.413,49.873 ; 10.864,13.208 cw(c10.864,14.22) 10.148,13.504 ccw(c10.864,14.22) 10.864,13.208 ; 10.864,13.208 ccw(c10.864,12.196) 10.148,12.912 cw(c10.864,12.196) 10.864,13.208 ; 11.403,13.208 cw(c11.403,12.901) 11.62,13.118 ccw(c11.403,12.901) 11.403,13.208 ; 11.403,13.208 ccw(c11.403,13.515) 11.62,13.298 cw(c11.403,13.515) 11.403,13.208 ; v1@11.477,13.208 cw(c11.477,14.833) 10.328,13.684 ccw(c11.477,14.833) v1@11.477,13.208 ; v1@11.477,13.208 ccw(c11.477,11.583) 10.328,12.732 cw(c11.477,11.583) v1@11.477,13.208 ; 15.87,64.13 cw(c15.24,64.76) 15.24,63.869 ccw(c15.24,64.76) 15.87,64.13 ; 15.87,64.13 ccw(c16.5,63.5) 15.609,63.5 cw(c16.5,63.5) 15.87,64.13 ; 16.304,64.564 cw(c15.24,65.627) 15.24,64.123 ccw(c15.24,65.627) 16.304,64.564 ; 16.304,64.564 ccw(c17.367,63.5) 15.863,63.5 cw(c17.367,63.5) 16.304,64.564
  Bottom Layer w0.254: v1(11.709,13.208) 11.709,48.209 12.243,48.743 12.243,60.503 P1.9@15.24,63.5 ; 11.709,13.515 cw(c11.403,13.515) 11.62,13.298 ccw(c11.403,13.515) 11.709,13.515 ; 11.709,13.515 ccw(c12.016,13.515) 11.799,13.298 cw(c12.016,13.515) 11.709,13.515 ; 14.176,62.436 cw(c15.24,61.373) 15.24,62.877 ccw(c15.24,61.373) 14.176,62.436 ; 14.176,62.436 ccw(c13.113,63.5) 14.617,63.5 cw(c13.113,63.5) 14.176,62.436 ; 14.61,62.87 cw(c15.24,62.24) 15.24,63.131 ccw(c15.24,62.24) 14.61,62.87 ; 14.61,62.87 ccw(c13.98,63.5) 14.871,63.5 cw(c13.98,63.5) 14.61,62.87
KEY2: K2.1 P1.10 U1.2 | length 116.1
  Top Layer w0.254: K2.1@9.652,17.272 v1(12.294,17.272) ; P1.10@17.78,63.5 40.208,63.5 42.824,60.884 42.824,50.755 U1.2@44.06,49.52 ; 10.864,17.272 cw(c10.864,18.284) 10.148,17.568 ccw(c10.864,18.284) 10.864,17.272 ; 10.864,17.272 ccw(c10.864,16.26) 10.148,16.976 cw(c10.864,16.26) 10.864,17.272 ; 11.477,17.272 cw(c11.477,18.897) 10.328,17.748 ccw(c11.477,18.897) 11.477,17.272 ; 11.477,17.272 ccw(c11.477,15.647) 10.328,16.796 cw(c11.477,15.647) 11.477,17.272 ; 11.987,17.272 cw(c11.987,16.965) 12.204,17.182 ccw(c11.987,16.965) 11.987,17.272 ; 11.987,17.272 ccw(c11.987,17.579) 12.204,17.362 cw(c11.987,17.579) 11.987,17.272 ; 18.671,63.5 cw(c18.671,64.391) 18.041,63.761 ccw(c18.671,64.391) 18.671,63.5 ; 18.671,63.5 ccw(c18.671,62.609) 18.041,63.239 cw(c18.671,62.609) 18.671,63.5 ; 19.284,63.5 cw(c19.284,65.004) 18.221,63.941 ccw(c19.284,65.004) 19.284,63.5 ; 19.284,63.5 ccw(c19.284,61.996) 18.221,63.059 cw(c19.284,61.996) 19.284,63.5
  Bottom Layer w0.254: v1(12.294,17.272) 12.294,47.967 12.827,48.501 12.827,60.198 14.808,62.179 15.85,62.179 17.17,63.5 P1.10@17.78,63.5 ; 12.294,17.579 cw(c11.987,17.579) 12.204,17.362 ccw(c11.987,17.579) 12.294,17.579 ; 12.294,17.579 ccw(c12.6,17.579) 12.383,17.362 cw(c12.6,17.579) 12.294,17.579 ; 16.109,62.439 cw(c17.78,60.768) 17.78,63.131 ccw(c17.78,60.768) 16.109,62.439 ; 16.543,62.873 cw(c17.78,61.636) 17.78,63.385 ccw(c17.78,61.636) 16.543,62.873 ; 16.977,63.306 cw(c17.78,62.503) 17.78,63.639 ccw(c17.78,62.503) 16.977,63.306
KEY3: K3.1 P1.11 U1.3 | length 109
  Top Layer w0.254: K3.1@9.652,21.336 v1(12.852,21.336) ; P1.11@15.24,60.96 16.485,62.205 40.157,62.205 42.342,60.02 42.342,50.53 U1.3@43.706,49.166 ; 10.864,21.336 cw(c10.864,22.348) 10.148,21.632 ccw(c10.864,22.348) 10.864,21.336 ; 10.864,21.336 ccw(c10.864,20.324) 10.148,21.04 cw(c10.864,20.324) 10.864,21.336 ; 11.477,21.336 cw(c11.477,22.961) 10.328,21.812 ccw(c11.477,22.961) 11.477,21.336 ; 11.477,21.336 ccw(c11.477,19.711) 10.328,20.86 cw(c11.477,19.711) 11.477,21.336 ; 12.546,21.336 cw(c12.546,21.029) 12.763,21.246 ccw(c12.546,21.029) 12.546,21.336 ; 12.546,21.336 ccw(c12.546,21.643) 12.763,21.426 cw(c12.546,21.643) 12.546,21.336 ; 15.87,61.59 cw(c15.24,62.22) 15.24,61.329 ccw(c15.24,62.22) 15.87,61.59 ; 15.87,61.59 ccw(c16.5,60.96) 15.609,60.96 cw(c16.5,60.96) 15.87,61.59 ; 16.304,62.024 cw(c15.24,63.087) 15.24,61.583 ccw(c15.24,63.087) 16.304,62.024 ; 16.304,62.024 ccw(c17.367,60.96) 15.863,60.96 cw(c17.367,60.96) 16.304,62.024
  Bottom Layer w0.254: v1(12.852,21.336) 12.852,47.736 13.386,48.269 13.386,59.106 P1.11@15.24,60.96 ; 12.852,21.643 cw(c12.546,21.643) 12.763,21.426 ccw(c12.546,21.643) 12.852,21.643 ; 12.852,21.643 ccw(c13.159,21.643) 12.942,21.426 cw(c13.159,21.643) 12.852,21.643 ; 14.176,59.896 cw(c15.24,58.833) 15.24,60.337 ccw(c15.24,58.833) 14.176,59.896 ; 14.176,59.896 ccw(c13.113,60.96) 14.617,60.96 cw(c13.113,60.96) 14.176,59.896 ; 14.61,60.33 cw(c15.24,59.7) 15.24,60.591 ccw(c15.24,59.7) 14.61,60.33 ; 14.61,60.33 ccw(c13.98,60.96) 14.871,60.96 cw(c13.98,60.96) 14.61,60.33
KEY4: K4.1 P1.12 U1.4 | length 108.2
  Top Layer w0.254: K4.1@9.652,25.4 v1(13.411,25.4) ; P1.12@17.78,60.96 40.081,60.96 41.885,59.157 41.885,50.281 U1.4@43.352,48.813 ; 10.864,25.4 cw(c10.864,26.412) 10.148,25.696 ccw(c10.864,26.412) 10.864,25.4 ; 10.864,25.4 ccw(c10.864,24.388) 10.148,25.104 cw(c10.864,24.388) 10.864,25.4 ; 11.477,25.4 cw(c11.477,27.025) 10.328,25.876 ccw(c11.477,27.025) 11.477,25.4 ; 11.477,25.4 ccw(c11.477,23.775) 10.328,24.924 cw(c11.477,23.775) 11.477,25.4 ; 13.105,25.4 cw(c13.105,25.093) 13.321,25.31 ccw(c13.105,25.093) 13.105,25.4 ; 13.105,25.4 ccw(c13.105,25.707) 13.321,25.49 cw(c13.105,25.707) 13.105,25.4 ; 18.671,60.96 cw(c18.671,61.851) 18.041,61.221 ccw(c18.671,61.851) 18.671,60.96 ; 18.671,60.96 ccw(c18.671,60.069) 18.041,60.699 cw(c18.671,60.069) 18.671,60.96 ; 19.284,60.96 cw(c19.284,62.464) 18.221,61.401 ccw(c19.284,62.464) 19.284,60.96 ; 19.284,60.96 ccw(c19.284,59.456) 18.221,60.519 cw(c19.284,59.456) 19.284,60.96
  Bottom Layer w0.254: v1(13.411,25.4) 13.411,47.504 13.945,48.038 13.945,58.903 14.707,59.665 15.646,59.665 16.942,60.96 P1.12@17.78,60.96 ; 13.411,25.707 cw(c13.105,25.707) 13.321,25.49 ccw(c13.105,25.707) 13.411,25.707 ; 13.411,25.707 ccw(c13.718,25.707) 13.501,25.49 cw(c13.718,25.707) 13.411,25.707 ; 15.719,59.737 cw(c17.78,57.677) 17.78,60.591 ccw(c17.78,57.677) 15.719,59.737 ; 16.153,60.171 cw(c17.78,58.544) 17.78,60.845 ccw(c17.78,58.544) 16.153,60.171 ; 16.586,60.605 cw(c17.78,59.411) 17.78,61.099 ccw(c17.78,59.411) 16.586,60.605 ; 17.02,61.038 cw(c17.78,60.278) 17.78,61.353 ccw(c17.78,60.278) 17.02,61.038
L-: J1.10 R17.1 U2.28 | length 71.8
  Top Layer w0.254: R17.1@58.422,95.504 v1(58.422,92.151) 58.422,90.905 59.162,90.165 U2.28@59.162,86.904 ; v1(91.973,88.57) 91.973,79.424 J1.10@93.571,77.826 ; 58.422,91.845 cw(c58.728,91.845) 58.511,92.061 ccw(c58.728,91.845) 58.422,91.845 ; 58.422,91.845 ccw(c58.115,91.845) 58.332,92.061 cw(c58.115,91.845) 58.422,91.845 ; 58.422,92.458 cw(c58.115,92.458) 58.332,92.241 ccw(c58.115,92.458) 58.422,92.458 ; 58.422,92.458 ccw(c58.728,92.458) 58.511,92.241 cw(c58.728,92.458) 58.422,92.458 ; 58.422,94.151 cw(c59.648,94.151) 58.781,95.018 ccw(c59.648,94.151) 58.422,94.151 ; 58.422,94.151 ccw(c57.195,94.151) 58.062,95.018 cw(c57.195,94.151) 58.422,94.151 ; 91.973,88.263 cw(c92.28,88.263) 92.063,88.48 ccw(c92.28,88.263) 91.973,88.263 ; 91.973,88.263 ccw(c91.667,88.263) 91.884,88.48 cw(c91.667,88.263) 91.973,88.263 ; 92.508,78.889 cw(c91.444,77.826) 92.948,77.826 ccw(c91.444,77.826) 92.508,78.889 ; 92.508,78.889 ccw(c93.571,79.953) 93.571,78.449 cw(c93.571,79.953) 92.508,78.889 ; 92.941,78.456 cw(c92.312,77.826) 93.202,77.826 ccw(c92.312,77.826) 92.941,78.456 ; 92.941,78.456 ccw(c93.571,79.085) 93.571,78.195 cw(c93.571,79.085) 92.941,78.456
  Bottom Layer w0.254: v1(58.422,92.151) 64.999,92.151 65.71,91.44 83.185,91.44 83.515,91.77 88.773,91.77 v1(91.973,88.57) ; 58.728,92.151 cw(c58.728,92.458) 58.511,92.241 ccw(c58.728,92.458) 58.728,92.151 ; 58.728,92.151 ccw(c58.728,91.845) 58.511,92.061 cw(c58.728,91.845) 58.728,92.151 ; 91.757,88.787 cw(c91.54,88.57) 91.846,88.57 ccw(c91.54,88.57) 91.757,88.787 ; 91.757,88.787 ccw(c91.973,89.003) 91.973,88.697 cw(c91.973,89.003) 91.757,88.787
LCD_BL: 2.4'/2.8'LCD.23 P1.49 U1.47 | length 71.5
  Top Layer w0.254: P1.49@15.24,12.7 16.485,13.945 27.381,13.945 v1(35.001,21.565) 42.24,28.804 42.24,30.695 U1.47@43.352,31.807 ; 15.87,13.33 cw(c15.24,13.96) 15.24,13.069 ccw(c15.24,13.96) 15.87,13.33 ; 15.87,13.33 ccw(c16.5,12.7) 15.609,12.7 cw(c16.5,12.7) 15.87,13.33 ; 16.304,13.764 cw(c15.24,14.827) 15.24,13.323 ccw(c15.24,14.827) 16.304,13.764 ; 16.304,13.764 ccw(c17.367,12.7) 15.863,12.7 cw(c17.367,12.7) 16.304,13.764 ; 34.784,21.348 cw(c35.001,21.131) 35.001,21.438 ccw(c35.001,21.131) 34.784,21.348 ; 34.784,21.348 ccw(c34.568,21.565) 34.874,21.565 cw(c34.568,21.565) 34.784,21.348 ; 35.218,21.781 cw(c35.001,21.998) 35.001,21.692 ccw(c35.001,21.998) 35.218,21.781 ; 35.218,21.781 ccw(c35.435,21.565) 35.128,21.565 cw(c35.435,21.565) 35.218,21.781
  Bottom Layer w0.254: v1(35.001,21.565) 34.976,21.59 34.9,21.59 36.347,20.142 2.4'/2.8'LCD.23@36.347,6.274 ; 36.347,7.255 cw(c35.366,7.255) 36.06,6.561 ccw(c35.366,7.255) 36.347,7.255 ; 36.347,7.255 ccw(c37.329,7.255) 36.635,6.561 cw(c37.329,7.255) 36.347,7.255 ; 36.347,7.868 cw(c34.753,7.868) 35.88,6.741 ccw(c34.753,7.868) 36.347,7.868 ; 36.347,7.868 ccw(c37.942,7.868) 36.814,6.741 cw(c37.942,7.868) 36.347,7.868 ; v1@35.128,21.565 ccw(c35.619,21.565) 35.272,21.218 cw(c35.619,21.565) v1@35.128,21.565
MCO1: P2.31 R41.1 U1.67 | length 83.5
  Top Layer w0.254: v1(50.817,37.812) U1.67@52.227,36.403 52.243,36.403 53.899,34.747 69.291,34.747 P2.31@70.104,35.56 ; 51.034,37.596 cw(c51.251,37.812) 50.944,37.812 ccw(c51.251,37.812) 51.034,37.596 ; 51.034,37.596 ccw(c50.817,37.379) 50.817,37.685 cw(c50.817,37.379) 51.034,37.596
  Bottom Layer w0.254: v1(49.278,95.504) 49.278,79.986 48.438,79.146 48.438,39.065 49.681,37.822 v1@50.808,37.822 ; 49.278,95.197 cw(c49.584,95.197) 49.367,95.414 ccw(c49.584,95.197) 49.278,95.197 ; 49.278,95.197 ccw(c48.971,95.197) 49.188,95.414 cw(c48.971,95.197) 49.278,95.197 ; 50.488,37.822 cw(c50.488,37.483) 50.727,37.723 ccw(c50.488,37.483) 50.488,37.822 ; 50.534,37.822 ccw(c50.534,38.096) 50.727,37.902 cw(c50.534,38.096) 50.534,37.822
NetBOOT_3: BOOT.3 R4.1 | length 14.3
  Top Layer w0.254: R4.1@7.95,79.983 BOOT.3@7.95,82.931 ; 7.95,81.209 cw(c6.724,81.209) 7.591,80.342 ccw(c6.724,81.209) 7.95,81.209 ; 7.95,81.209 ccw(c9.177,81.209) 8.309,80.342 cw(c9.177,81.209) 7.95,81.209 ; 7.95,81.427 cw(c9.454,81.427) 8.391,82.49 ccw(c9.454,81.427) 7.95,81.427 ; 7.95,81.427 ccw(c6.446,81.427) 7.51,82.49 cw(c6.446,81.427) 7.95,81.427 ; 7.95,82.04 cw(c8.841,82.04) 8.211,82.67 ccw(c8.841,82.04) 7.95,82.04 ; 7.95,82.04 ccw(c7.059,82.04) 7.689,82.67 cw(c7.059,82.04) 7.95,82.04
NetBOOT_4: BOOT.4 R5.1 | length 14.5
  Top Layer w0.254: BOOT.4@7.95,85.471 R5.1@7.95,88.619 ; 7.95,86.362 cw(c7.059,86.362) 7.689,85.732 ccw(c7.059,86.362) 7.95,86.362 ; 7.95,86.362 ccw(c8.841,86.362) 8.211,85.732 cw(c8.841,86.362) 7.95,86.362 ; 7.95,86.975 cw(c6.446,86.975) 7.51,85.912 ccw(c6.446,86.975) 7.95,86.975 ; 7.95,86.975 ccw(c9.454,86.975) 8.391,85.912 cw(c9.454,86.975) 7.95,86.975 ; 7.95,87.393 cw(c9.177,87.393) 8.309,88.26 ccw(c9.177,87.393) 7.95,87.393 ; 7.95,87.393 ccw(c6.724,87.393) 7.591,88.26 cw(c6.724,87.393) 7.95,87.393
NetC1_2: C1.2 U1.12 Y1.1 | length 26.5
  Top Layer w0.254: Y1.1@30.759,55.55 33.245,53.064 35.256,53.064 38.236,50.085 38.236,48.272 U1.12@40.524,45.984 ; 31.627,54.683 cw(c32.494,55.55) 31.267,55.55 ccw(c32.494,55.55) 31.627,54.683 ; 31.627,54.683 ccw(c30.759,53.815) 30.759,55.042 cw(c30.759,53.815) 31.627,54.683
  Bottom Layer w0.254: C1.2@27.618,55.641 28.568,56.591 29.718,56.591 Y1.1@30.759,55.55 ; 29.892,56.417 cw(c29.025,55.55) 30.251,55.55 ccw(c29.025,55.55) 29.892,56.417 ; 29.892,56.417 ccw(c30.759,57.284) 30.759,56.058 cw(c30.759,57.284) 29.892,56.417
NetC2_1: C2.1 U1.13 Y1.2 | length 21.4
  Top Layer w0.254: Y1.2@34.21,52.099 35.322,50.987 36.687,50.987 37.779,49.895 37.779,48.022 U1.13@40.17,45.631 ; 35.077,51.232 cw(c35.945,52.099) 34.718,52.099 ccw(c35.945,52.099) 35.077,51.232 ; 35.077,51.232 ccw(c34.21,50.365) 34.21,51.591 cw(c34.21,50.365) 35.077,51.232
  Bottom Layer w0.254: Y1.2@34.21,52.099 35.255,51.054 35.255,49.886 C2.1@34.314,48.945 ; 35.077,51.232 cw(c35.945,52.099) 34.718,52.099 ccw(c35.945,52.099) 35.077,51.232 ; 35.077,51.232 ccw(c34.21,50.365) 34.21,51.591 cw(c34.21,50.365) 35.077,51.232
NetC3_1: C3.1 U1.8 Y2.2 | length 17.2
  Top Layer w0.254: Y2.2@39.893,55.032 40.792,54.132 40.792,48.544 U1.8@41.938,47.399
  Bottom Layer w0.254: Y2.2@39.893,55.032 39.919,55.032 C3.1@41.274,56.387 ; 40.407,55.52 cw(c41.274,54.652) 41.274,55.879 ccw(c41.274,54.652) 40.407,55.52 ; 40.407,55.52 ccw(c39.539,56.387) 40.766,56.387 cw(c39.539,56.387) 40.407,55.52 ; Y2.2@39.893,55.413 ccw(c39.893,56.394) 40.587,55.7 cw(c39.893,56.394) Y2.2@39.893,55.413 ; Y2.2@40.274,55.032 cw(c41.133,55.032) 40.526,55.639 ccw(c41.133,55.032) Y2.2@40.274,55.032
NetC4_1: C4.1 U1.9 Y2.1 | length 19.8
  Top Layer w0.254: Y2.1@38.887,54.026 40.234,52.68 40.234,48.396 U1.9@41.585,47.045 ; 39.628,53.286 cw(c40.278,53.936) 39.358,53.936 ccw(c40.278,53.936) 39.628,53.286 ; 39.628,53.286 ccw(c38.977,52.635) 38.977,53.555 cw(c38.977,52.635) 39.628,53.286
  Bottom Layer w0.254: C4.1@37.438,52.577 Y2.1@38.887,54.026 ; 38.237,53.375 cw(c38.887,52.725) 38.887,53.645 ccw(c38.887,52.725) 38.237,53.375 ; 38.237,53.375 ccw(c37.587,54.026) 38.506,54.026 cw(c37.587,54.026) 38.237,53.375 ; 38.306,53.444 cw(c37.438,54.311) 37.438,53.085 ccw(c37.438,54.311) 38.306,53.444 ; 38.306,53.444 ccw(c39.173,52.577) 37.946,52.577 cw(c39.173,52.577) 38.306,53.444
NetC5_1: C5.1 U1.49 | length 22.6
  Top Layer w0.254: v1(37.211,21.996) 43.286,28.071 43.286,30.326 U1.49@44.06,31.1 ; 37.428,22.213 cw(c37.211,22.43) 37.211,22.123 ccw(c37.211,22.43) 37.428,22.213 ; 37.428,22.213 ccw(c37.645,21.996) 37.338,21.996 cw(c37.645,21.996) 37.428,22.213 ; U1.49@43.442,30.482 ccw(c43.819,30.105) 43.286,30.105 cw(c43.819,30.105) U1.49@43.442,30.482 ; U1.49@43.442,30.482 ccw(c43.52,30.261) 43.286,30.261 cw(c43.52,30.261) U1.49@43.442,30.482
  Bottom Layer w0.254: C5.1@33.238,24.881 34.326,24.881 ; v1(37.211,21.996) 34.326,24.881 ; 34.326,24.881 cw(c34.326,25.346) 33.902,25.156 ccw(c34.326,25.346) 34.326,24.881 ; 34.326,24.881 ccw(c34.326,24.416) 33.902,24.606 cw(c34.326,24.416) 34.326,24.881 ; 36.994,22.213 cw(c36.777,21.996) 37.084,21.996 ccw(c36.777,21.996) 36.994,22.213 ; 36.994,22.213 ccw(c37.211,22.43) 37.211,22.123 cw(c37.211,22.43) 36.994,22.213
NetC6_1: C6.1 U1.73 | length 9.1
  Top Layer w0.254: U1.73@54.348,38.524 55.458,37.414 58.496,37.414 v1(60.96,39.878) ; 60.743,39.661 cw(c60.96,39.444) 60.96,39.751 ccw(c60.96,39.444) 60.743,39.661 ; 60.743,39.661 ccw(c60.526,39.878) 60.833,39.878 cw(c60.526,39.878) 60.743,39.661
NetC20_1: C20.1 C21.1 C22.1 C23.1 U2.18 U2.23 U2.37 | length 98.4
  Top Layer w0.254: U2.37@53.812,85.554 52.546,85.554 52.172,85.928 C20.1@52.172,87.276 54.024,87.276 v1(54.026,87.274) ; U2.18@62.012,82.554 64.647,82.554 65.075,82.982 67.412,82.982 68.378,82.015 C21.1@69.901,82.015 C23.1@69.901,85.319 ; U2.23@62.012,85.054 63.794,85.054 64.084,85.344 v1(65.43,85.344) v1(65.43,86.792) ; v1(67.589,85.623) 69.596,85.623 C23.1@69.901,85.319 ; C23.1@69.636,85.054 C23.1@69.901,85.319 ; C22.1@69.926,88.67 69.901,88.644 C23.1@69.901,85.319 ; 52.172,86.05 cw(c53.398,86.05) 52.531,86.917 ccw(c53.398,86.05) 52.172,86.05 ; 52.172,86.05 ccw(c50.945,86.05) 51.812,86.917 cw(c50.945,86.05) 52.172,86.05 ; 53.525,87.276 cw(c53.525,88.502) 52.658,87.635 ccw(c53.525,88.502) 53.525,87.276 ; 53.525,87.276 ccw(c53.525,86.05) 52.658,86.917 cw(c53.525,86.05) 53.525,87.276 ; 65.124,85.344 cw(c65.124,85.037) 65.341,85.254 ccw(c65.124,85.037) 65.124,85.344 ; 65.124,85.344 ccw(c65.124,85.651) v1@65.341,85.434 ; 65.124,85.344 ccw(c65.124,85.651) v1@65.341,85.434 ; v1@65.341,85.434 ccw(c65.124,85.651) 65.43,85.651 ; v1@65.341,85.434 ccw(c65.124,85.651) 65.43,85.651 ; 65.43,85.651 ccw(c65.737,85.651) 65.52,85.434 cw(c65.737,85.651) 65.43,85.651 ; 65.43,86.485 cw(c65.737,86.485) 65.52,86.702 ccw(c65.737,86.485) 65.43,86.485 ; 65.43,86.485 ccw(c65.124,86.485) 65.341,86.702 cw(c65.124,86.485) 65.43,86.485 ; 67.896,85.623 cw(c67.896,85.93) 67.679,85.713 ccw(c67.896,85.93) 67.896,85.623 ; 67.896,85.623 ccw(c67.896,85.317) 67.679,85.534 cw(c67.896,85.317) 67.896,85.623 ; 68.547,82.015 cw(c68.547,80.789) 69.415,81.656 ccw(c68.547,80.789) 68.547,82.015 ; 68.547,82.015 ccw(c68.547,83.241) 69.415,82.374 cw(c68.547,83.241) 68.547,82.015 ; C23.1@69.39,86.28 cw(c67.805,87.865) 67.805,85.623 ccw(c67.805,87.865) C23.1@69.39,86.28 ; C23.1@69.39,86.28 ccw(c68.155,87.514) 69.901,87.514 ; C23.1@69.39,86.28 ccw(c68.155,87.514) 69.901,87.514 ; C23.1@69.569,86.1 cw(c68.418,87.251) 68.418,85.623 ccw(c68.418,87.251) C23.1@69.569,86.1 ; C23.1@69.569,86.1 ccw(c68.769,86.901) 69.901,86.901 ; C23.1@69.569,86.1 ccw(c68.769,86.901) 69.901,86.901 ; 69.901,83.123 cw(c71.646,83.123) 70.412,84.357 ccw(c71.646,83.123) 69.901,83.123 ; 69.901,83.123 ccw(c68.155,83.123) 69.39,84.357 cw(c68.155,83.123) 69.901,83.123 ; 69.901,83.241 cw(c68.674,83.241) 69.542,82.374 ccw(c68.674,83.241) 69.901,83.241 ; 69.901,83.241 ccw(c71.127,83.241) 70.26,82.374 cw(c71.127,83.241) 69.901,83.241 ; 69.901,83.736 cw(c71.033,83.736) 70.232,84.537 ccw(c71.033,83.736) 69.901,83.736 ; 69.901,83.736 ccw(c68.769,83.736) 69.569,84.537 cw(c68.769,83.736) 69.901,83.736 ; 69.901,86.901 ccw(c71.033,86.901) 70.232,86.1 cw(c71.033,86.901) 69.901,86.901 ; 69.901,87.514 ccw(c71.646,87.514) 70.412,86.28 cw(c71.646,87.514) 69.901,87.514 ; 53.715,87.276 cw(c53.715,86.964) 53.936,87.185 ccw(c53.715,86.964) 53.715,87.276 ; 53.723,87.276 ccw(c53.723,87.577) 53.936,87.364 cw(c53.723,87.577) 53.723,87.276 ; 68.506,85.623 cw(c68.506,84.374) 69.39,85.257 ccw(c68.506,84.374) 68.506,85.623 ; 69.031,85.623 ccw(c69.031,86.638) 69.749,85.921 cw(c69.031,86.638) 69.031,85.623 ; C22.1@69.567,88.311 cw(c68.761,87.505) 69.901,87.505 ccw(c68.761,87.505) C22.1@69.567,88.311 ; 69.901,87.382 cw(c71.214,87.382) 70.285,88.311 ccw(c71.214,87.382) 69.901,87.382 ; 69.901,87.995 cw(c70.601,87.995) 70.106,88.49 ccw(c70.601,87.995) 69.901,87.995
  Bottom Layer w0.254: v1(54.026,87.274) 55.524,85.776 62.636,85.776 63.652,86.792 v1(65.43,86.792) ; v1(65.43,85.344) 67.31,85.344 v1(67.589,85.623) ; 54.243,87.058 cw(c54.459,87.274) 54.153,87.274 ccw(c54.459,87.274) 54.243,87.058 ; 54.243,87.058 ccw(c54.026,86.841) 54.026,87.147 cw(c54.026,86.841) 54.243,87.058 ; 65.124,86.792 cw(c65.124,86.485) 65.341,86.702 ccw(c65.124,86.485) 65.124,86.792 ; 65.124,86.792 ccw(c65.124,87.098) 65.341,86.882 cw(c65.124,87.098) 65.124,86.792 ; 65.737,85.344 cw(c65.737,85.651) 65.52,85.434 ccw(c65.737,85.651) 65.737,85.344 ; 65.737,85.344 ccw(c65.737,85.037) 65.52,85.254 cw(c65.737,85.037) 65.737,85.344
NetC32_1: C32.1 C33.1 L1.2 R31.1 | length 26.7
  Bottom Layer w0.508: C33.1@32.842,78.738 C32.1@32.842,81.786 R31.1@32.842,84.834 L1.2@36.144,84.834 ; 32.842,79.658 cw(c31.922,79.658) 32.573,79.008 ccw(c31.922,79.658) 32.842,79.658 ; 32.842,79.658 ccw(c33.762,79.658) 33.112,79.008 cw(c33.762,79.658) 32.842,79.658 ; 32.842,80.867 cw(c33.762,80.867) 33.112,81.517 ccw(c33.762,80.867) 32.842,80.867 ; 32.842,80.867 ccw(c31.922,80.867) 32.573,81.517 cw(c31.922,80.867) 32.842,80.867 ; 32.842,82.706 cw(c31.922,82.706) 32.573,82.056 ccw(c31.922,82.706) 32.842,82.706 ; 32.842,82.706 ccw(c33.762,82.706) 33.112,82.056 cw(c33.762,82.706) 32.842,82.706 ; 32.842,83.915 cw(c33.762,83.915) 33.112,84.565 ccw(c33.762,83.915) 32.842,83.915 ; 32.842,83.915 ccw(c31.922,83.915) 32.573,84.565 cw(c31.922,83.915) 32.842,83.915 ; 33.889,84.834 cw(c33.889,85.754) 33.239,85.104 ccw(c33.889,85.754) 33.889,84.834 ; 33.889,84.834 ccw(c33.889,83.915) 33.239,84.565 cw(c33.889,83.915) 33.889,84.834 ; 35.097,84.834 cw(c35.097,83.915) 35.748,84.565 ccw(c35.097,83.915) 35.097,84.834 ; 35.097,84.834 ccw(c35.097,85.754) 35.748,85.104 cw(c35.097,85.754) 35.097,84.834
NetC40_1: C40.1 U10.8 Y3.2 | length 19.1
  Top Layer w0.254: U10.8@78.502,7.061 78.502,3.029 Y3.2@78.508,3.023 ; 78.502,6.644 cw(c78.92,6.644) 78.625,6.939 ccw(c78.92,6.644) 78.502,6.644 ; 78.502,6.644 ccw(c78.085,6.644) 78.38,6.939 cw(c78.085,6.644) 78.502,6.644 ; Y3.2@78.149,3.382 ccw(c77.296,4.235) 78.502,4.235 cw(c77.296,4.235) Y3.2@78.149,3.382 ; 78.502,4.263 ccw(c79.749,4.263) 78.867,3.382 cw(c79.749,4.263) 78.502,4.263
  Bottom Layer w0.254: C40.1@76.327,3.021 Y3.2@78.507,3.021 ; 77.68,3.021 cw(c77.68,4.247) 76.813,3.38 ccw(c77.68,4.247) 77.68,3.021 ; 77.68,3.021 ccw(c77.68,1.795) 76.813,2.662 cw(c77.68,1.795) 77.68,3.021 ; 77.278,3.021 ccw(c77.278,4.253) 78.149,3.382 cw(c77.278,4.253) 77.278,3.021 ; 77.286,3.021 cw(c77.286,1.8) 78.149,2.663 ccw(c77.286,1.8) 77.286,3.021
